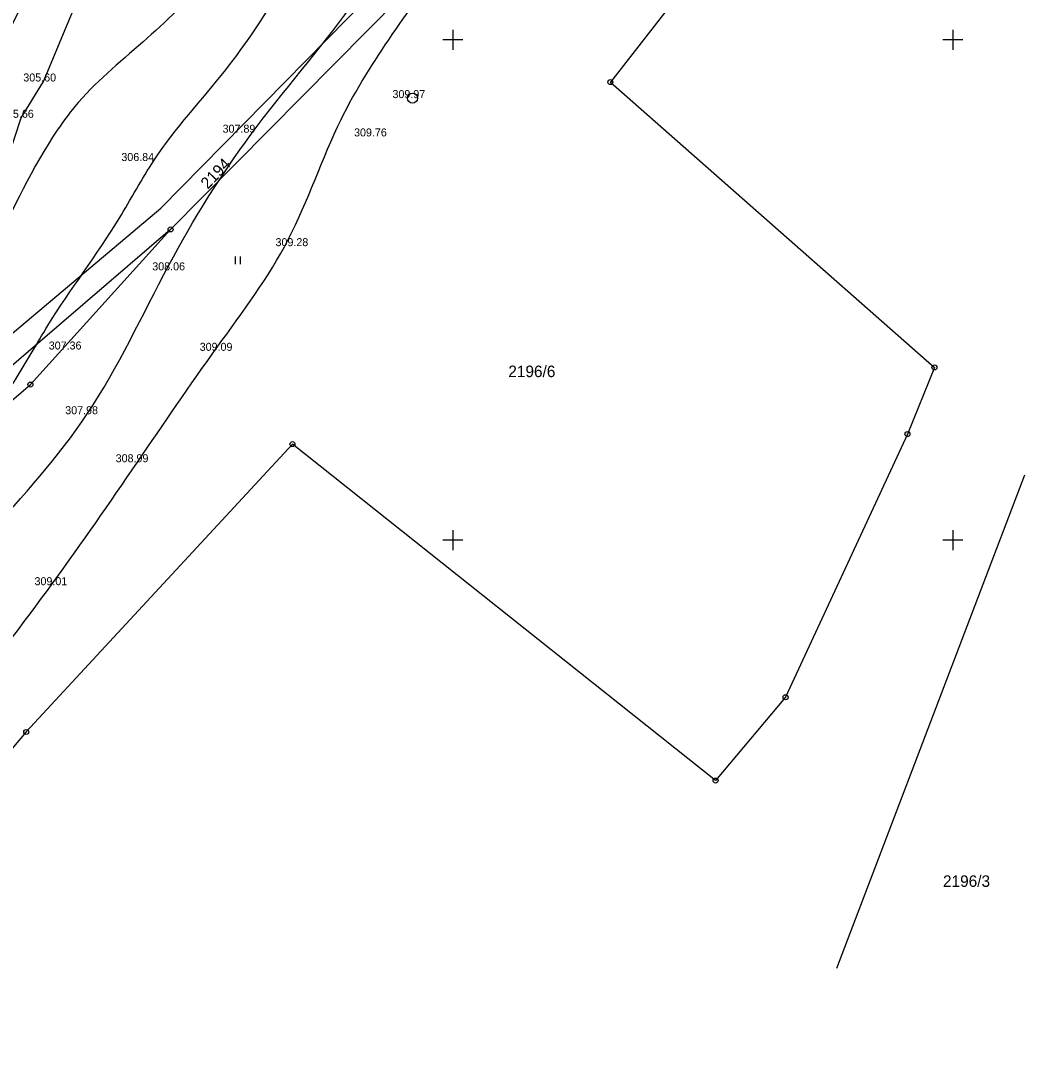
# Model space of a CAD drawing. Extents: x -504375 to -503125, y -1118000 to -1116474.
# Drawn here: x -503643.2 to -503541.3, y -1117200.4 to -1117098.1 of the extents above; entities that cross this region are included whole.
import ezdxf

# ---------------------------------------------------------------- set-up
doc = ezdxf.new("R2010")
doc.units = 0
for name, color, linetype in [('Druhy povrchů', 7, 'Continuous'), ('Neidetifikované', 7, 'Continuous'), ('Podkladové mapy', 7, 'Continuous'), ('Vrstva 34', 7, 'Continuous'), ('Vrstva 48', 7, 'Continuous'), ('Výškopis', 7, 'Continuous'), ('Výšky bodů plotr', 7, 'Continuous')]:
    doc.layers.add(name, color=color, linetype=linetype)

msp = doc.modelspace()

# ---------------------------------------------------------------- linework, layer by layer
at = {"layer": 'Druhy povrchů'}
for p, q in [((-503621.699, -1117122.407), (-503621.699, -1117121.657)), ((-503621.199, -1117122.407), (-503621.199, -1117121.657))]:
    msp.add_line(p, q, dxfattribs=at)
at = {"layer": 'Neidetifikované'}
msp.add_circle((-503604.02, -1117105.81), 0.5, dxfattribs=at)
at = {"layer": 'Podkladové mapy'}
for p, q in [((-503566.38, -1117081.28), (-503584.24, -1117104.21)), ((-503629.16, -1117116.82), (-503603.38, -1117090.56)), ((-503601.67, -1117092.1), (-503628.2, -1117118.94)), ((-503584.24, -1117104.21), (-503551.84, -1117132.73)), ((-503646.84, -1117131.67), (-503629.16, -1117116.82)), ((-503628.2, -1117118.94), (-503646.73, -1117134.84)), ((-503642.21, -1117134.44), (-503628.2, -1117118.94)), ((-503551.84, -1117132.73), (-503554.54, -1117139.39)), ((-503650.01, -1117141.08), (-503642.21, -1117134.44)), ((-503554.54, -1117139.39), (-503566.72, -1117165.7)), ((-503616.02, -1117140.4), (-503642.63, -1117169.17)), ((-503573.72, -1117174.02), (-503616.02, -1117140.4)), ((-503561.605, -1117192.787), (-503542.802, -1117143.469)), ((-503566.72, -1117165.7), (-503573.72, -1117174.02)), ((-503642.63, -1117169.17), (-503669.37, -1117200.41))]:
    msp.add_line(p, q, dxfattribs=at)
for centre, radius in [((-503584.24, -1117104.21), 0.25), ((-503584.24, -1117104.21), 0.005), ((-503628.2, -1117118.94), 0.25), ((-503628.2, -1117118.94), 0.005), ((-503551.84, -1117132.73), 0.25), ((-503551.84, -1117132.73), 0.005), ((-503642.21, -1117134.44), 0.25), ((-503642.21, -1117134.44), 0.005), ((-503554.54, -1117139.39), 0.25), ((-503554.54, -1117139.39), 0.005), ((-503616.02, -1117140.4), 0.25), ((-503616.02, -1117140.4), 0.005), ((-503566.72, -1117165.7), 0.25), ((-503566.72, -1117165.7), 0.005), ((-503642.63, -1117169.17), 0.25), ((-503642.63, -1117169.17), 0.005), ((-503573.72, -1117174.02), 0.25), ((-503573.72, -1117174.02), 0.005)]:
    msp.add_circle(centre, radius, dxfattribs=at)
at = {"layer": 'Vrstva 34'}
for p, q in [((-503600, -1117099), (-503600, -1117101)), ((-503550, -1117099), (-503550, -1117101)), ((-503599, -1117100), (-503601, -1117100)), ((-503549, -1117100), (-503551, -1117100)), ((-503600, -1117149), (-503600, -1117151)), ((-503550, -1117149), (-503550, -1117151)), ((-503599, -1117150), (-503601, -1117150)), ((-503549, -1117150), (-503551, -1117150))]:
    msp.add_line(p, q, dxfattribs=at)
at = {"layer": 'Vrstva 48'}
for points in [[(-503583.436, -1116916.735), (-503565.222, -1116898.002), (-503545.734, -1116881.633), (-503534.572, -1116870.778), (-503513.205, -1116846.809), (-503510.867, -1116843.732), (-503510.418, -1116843.732), (-503511.603, -1116846.232), (-503518.586, -1116862.77), (-503523.84, -1116880.397), (-503523.84, -1116881.294), (-503515.357, -1116898.665), (-503516.275, -1116901.249), (-503527.394, -1116929.845), (-503527.394, -1116936.169), (-503527.485, -1116936.022), (-503531.377, -1116947.63), (-503532.293, -1116950.302), (-503533.896, -1116960.764), (-503542.598, -1116970.081), (-503552.37, -1116992.445), (-503555.496, -1116996.72), (-503562.532, -1117003.134), (-503574.935, -1117012.154), (-503576.446, -1117014.604), (-503591.634, -1117036.568), (-503596.086, -1117041.635), (-503600.171, -1117047.806), (-503611.566, -1117069.423), (-503612.057, -1117071.221), (-503614.181, -1117072.938), (-503624.76, -1117093.42), (-503637.766, -1117106.652), (-503639.522, -1117109.013), (-503645.943, -1117120.982), (-503647.205, -1117123.178), (-503648.851, -1117124.99), (-503653.281, -1117132.788), (-503655.18, -1117135.25), (-503664.808, -1117144.375), (-503670.8, -1117145.499), (-503672.957, -1117151.15), (-503675.518, -1117162.241), (-503680.888, -1117175.407), (-503686.593, -1117176.265), (-503690.913, -1117183.112)], [(-503681.581, -1117189.358), (-503677.862, -1117181.382), (-503666.722, -1117185.997), (-503660.312, -1117176.769), (-503662.273, -1117171.205), (-503665.544, -1117166.288), (-503664.496, -1117159.63), (-503663.424, -1117157.82), (-503656.724, -1117146.894), (-503651.699, -1117143.274), (-503642.136, -1117131.351), (-503640.456, -1117128.532), (-503633.339, -1117117.852), (-503629.848, -1117112.023), (-503622.694, -1117102.978), (-503617.219, -1117095.012), (-503609.076, -1117080.347), (-503600.768, -1117066.026), (-503593.131, -1117053.049), (-503583.142, -1117034.879)], [(-503670.377, -1117191.619), (-503669.68, -1117189.038), (-503667.476, -1117187.838), (-503659.224, -1117178.665), (-503659.729, -1117171.664), (-503658.467, -1117166.241), (-503646.499, -1117149.509), (-503636.524, -1117137.367), (-503628.369, -1117122.514), (-503620.153, -1117109.423), (-503610.19, -1117096.668), (-503601.485, -1117082.212), (-503593.478, -1117067.759), (-503585.924, -1117054.445), (-503581.971, -1117047.028)], [(-503663.774, -1117189.171), (-503657.669, -1117182.299), (-503653.803, -1117173.825), (-503650.734, -1117168.851), (-503649.206, -1117166.706), (-503639.945, -1117154.236), (-503631.523, -1117142.215), (-503623.535, -1117130.705), (-503616.437, -1117119.955), (-503611.15, -1117107.935), (-503600.425, -1117091.261), (-503593.212, -1117078.753), (-503585.366, -1117064.793), (-503579.769, -1117055.757)], [(-503632.866, -1117079.324), (-503648.483, -1117110.842), (-503649.96, -1117118.382), (-503650.49, -1117120.413), (-503659.36, -1117127.451), (-503663.602, -1117129.909)]]:
    msp.add_spline(points, degree=3, dxfattribs=at)
at = {"layer": 'Výškopis'}
for points in [[(-503643.15, -1117107.78), (-503640.92, -1117104.15), (-503633.77, -1117087.02)], [(-503647.85, -1117122), (-503643.15, -1117107.78)]]:
    msp.add_lwpolyline(points, dxfattribs=at)

# ---------------------------------------------------------------- texts
at = {"layer": 'Podkladové mapy'}
msp.add_text('2194', height=1.15, rotation=46.33218, dxfattribs=at).set_placement((-503624.48, -1117114.97))
for s, p in [('2196/6', (-503594.44, -1117133.7)), ('2196/3', (-503550.989, -1117184.652))]:
    msp.add_text(s, height=1.15, dxfattribs=at).set_placement(p)
at = {"layer": 'Výšky bodů plotr'}
for s, p in [('305.60 ', (-503642.92, -1117104.15)), ('309.97 ', (-503606.02, -1117105.81)), ('305.66 ', (-503645.15, -1117107.78)), ('307.89 ', (-503623, -1117109.27)), ('309.76 ', (-503609.86, -1117109.64)), ('306.84 ', (-503633.12, -1117112.1)), ('309.28 ', (-503617.71, -1117120.61)), ('308.06 ', (-503630.03, -1117123.03)), ('307.36 ', (-503640.38, -1117130.94)), ('309.09 ', (-503625.29, -1117131.07)), ('307.98 ', (-503638.73, -1117137.41)), ('308.99 ', (-503633.69, -1117142.21)), ('309.01 ', (-503641.8, -1117154.5))]:
    msp.add_text(s, height=0.8, dxfattribs=at).set_placement(p)

doc.saveas('drawing.dxf')
